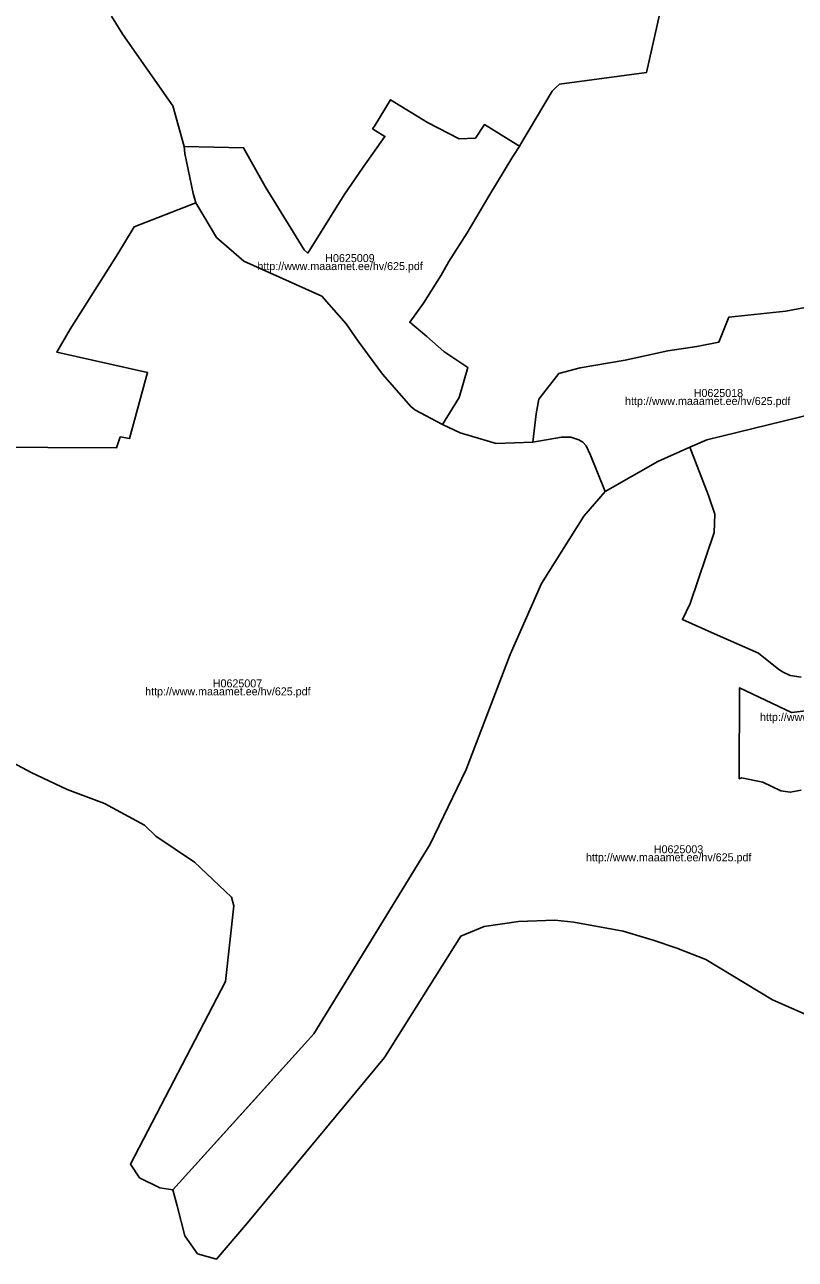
# Model space of a CAD drawing. Extents: x 369010 to 739155, y 6377141 to 6634081.
# Drawn here: x 526588 to 528995, y 6469557 to 6473413 of the extents above; entities that cross this region are included whole.
import ezdxf

# ---------------------------------------------------------------- set-up
doc = ezdxf.new("R2010")
doc.units = 0
for name, color, linetype in [('H_LINK', 7, 'Continuous'), ('H_PIIR', 7, 'Continuous'), ('H_TUNNUS', 7, 'Continuous')]:
    doc.layers.add(name, color=color, linetype=linetype)

msp = doc.modelspace()

# ---------------------------------------------------------------- linework, layer by layer
at = {"layer": 'H_PIIR'}
for points in [[(528589.67, 6473527.89), (528530.48, 6473264.36), (528259.09, 6473227.1101), (528245.84, 6473216.34), (528236.26, 6473205.33), (528138.15, 6473040.7199), (528134.2699, 6473034.71), (528128.4299, 6473036.44), (528023.96, 6473101.2399), (527996.25, 6473058.5499), (527944.85, 6473057.05), (527846.62, 6473108.2099), (527730.9099, 6473178.7101), (527680.44, 6473095.87), (527674.85, 6473088.32), (527683.43, 6473082.8099), (527713.5699, 6473064.27), (527645.0401, 6472967.87), (527586.53, 6472882.22), (527472.5101, 6472699.94), (527461.3, 6472710.46), (527339.8101, 6472907.9299), (527271.7301, 6473029.0799), (527086.72, 6473032.84), (527050.6, 6473159.6301), (526894.58, 6473382.58), (526859.94, 6473440.0801)], [(529107.85, 6472545.1301), (528965.28, 6472517.9799), (528787.09, 6472499.5701), (528756.01, 6472421.36), (528687.22, 6472408.04), (528596.64, 6472394.12), (528463.2701, 6472365.7501), (528323.67, 6472341.3799), (528256.85, 6472323.27), (528194.47, 6472243.2), (528185.5599, 6472197.94), (528175.2199, 6472109.09), (528061.15, 6472104.65), (527948.18, 6472137.89), (527893.4, 6472164.67), (527945.0901, 6472248.6201), (527972, 6472342.43), (527896.95, 6472392.1099), (527843.9699, 6472438.8899), (527791.0801, 6472483.8699), (527833.91, 6472543.07), (527889.0901, 6472630.4299), (527912.86, 6472673.8401), (527970.18, 6472763.52), (528038.15, 6472877.22), (528112.64, 6473001.22), (528134.2699, 6473034.71), (528138.15, 6473040.7199), (528236.26, 6473205.33), (528245.84, 6473216.34), (528259.09, 6473227.1101), (528530.48, 6473264.36), (528589.67, 6473527.89)], [(526859.94, 6473440.0801), (526894.58, 6473382.58), (527050.6, 6473159.6301), (527086.72, 6473032.84), (527088.48, 6473010.92), (527114.61, 6472885.94), (527122.61, 6472856.94), (526930.46, 6472782.2701), (526897.42, 6472726.61), (526874.49, 6472689.58), (526730.06, 6472462.0501), (526688.4401, 6472390.68), (526972.2499, 6472326.9799), (526916.03, 6472120.19), (526886.7599, 6472125.84), (526874.8201, 6472091.0601), (526445.13, 6472093.3199)], [(526445.13, 6472093.3199), (526874.8201, 6472091.0601), (526886.7599, 6472125.84), (526916.03, 6472120.19), (526972.2499, 6472326.9799), (526688.4401, 6472390.68), (526730.06, 6472462.0501), (526874.49, 6472689.58), (526897.42, 6472726.61), (526930.46, 6472782.2701), (527122.61, 6472856.94), (527147.33, 6472815.47), (527187.1, 6472748.7399), (527272.3801, 6472674.51), (527384.2401, 6472624.6599), (527516.04, 6472564.8301), (527592.4599, 6472478.42), (527630.32, 6472424.83), (527705.6301, 6472321.7999), (527794.16, 6472220.2299), (527806.39, 6472210.5501), (527893.4, 6472164.67), (527948.18, 6472137.89), (528061.15, 6472104.65), (528175.2199, 6472109.09), (528265.2399, 6472124.3999), (528294.55, 6472124.7), (528319.5201, 6472116.55), (528332, 6472109.11), (528342.19, 6472097.3901), (528355.7499, 6472068.5301), (528400.9401, 6471955.5101), (528334.4899, 6471877.73), (528202.7, 6471667.88), (528104.13, 6471446.31), (527966.79, 6471086.25), (527855.2205, 6470853.5011), (527491.8389, 6470260.7752), (527050.513, 6469773.4117), (527010.8255, 6469779.7617), (526947.3253, 6469811.5118), (526918.7503, 6469854.3744), (527215.6134, 6470424.288), (527241.0134, 6470660.826), (527234.5083, 6470688.3758), (527118.7757, 6470797.3512), (526998.3927, 6470878.6112), (526962.4093, 6470912.4779), (526837.5257, 6470980.2114), (526721.1088, 6471024.6615), (526608.9253, 6471077.5782), (526481.925, 6471145.3117)], [(529101.44, 6472210.1), (528718.62, 6472116.9799), (528665.93, 6472093.2999), (528565.9601, 6472048.3501), (528400.9401, 6471955.5101), (528355.7499, 6472068.5301), (528342.19, 6472097.3901), (528332, 6472109.11), (528319.5201, 6472116.55), (528294.55, 6472124.7), (528265.2399, 6472124.3999), (528175.2199, 6472109.09), (528185.5599, 6472197.94), (528194.47, 6472243.2), (528256.85, 6472323.27), (528323.67, 6472341.3799), (528463.2701, 6472365.7501), (528596.64, 6472394.12), (528687.22, 6472408.04), (528756.01, 6472421.36), (528787.09, 6472499.5701), (528965.28, 6472517.9799), (529107.85, 6472545.1301)], [(529013.18, 6471374.9899), (528979.0901, 6471380.45), (528956.74, 6471390.73), (528943.3401, 6471398.82), (528879.8201, 6471450.15), (528742.82, 6471510.14), (528642.6501, 6471554.9899), (528667.18, 6471605.6799), (528741.49, 6471827.2899), (528743.76, 6471884.14), (528724.0501, 6471942.44), (528665.93, 6472093.2999), (528718.62, 6472116.9799), (529101.44, 6472210.1)], [(529239.161, 6470228.233), (528923.777, 6470366.8749), (528715.8935, 6470493.3196), (528625.4059, 6470528.2447), (528550.7932, 6470553.6447), (528457.1305, 6470582.2198), (528302.922, 6470609.8737), (528244.4051, 6470615.5573), (528130.1049, 6470612.3823), (528023.7422, 6470596.5073), (527950.717, 6470566.3447), (527712.5915, 6470186.9315), (527283.9657, 6469670.993), (527187.128, 6469556.6927), (527128.3904, 6469574.1553), (527088.7028, 6469629.7179), (527064.8902, 6469723.3806), (527050.513, 6469773.4117), (527299.428, 6470048.2926), (527491.8389, 6470260.7752), (527581.0692, 6470406.3222), (527855.2205, 6470853.5011), (527966.79, 6471086.25), (528104.13, 6471446.31), (528202.7, 6471667.88), (528334.4899, 6471877.73), (528400.9401, 6471955.5101), (528565.9601, 6472048.3501), (528665.93, 6472093.2999), (528724.0501, 6471942.44), (528743.76, 6471884.14), (528741.49, 6471827.2899), (528667.18, 6471605.6799), (528642.6501, 6471554.9899), (528742.82, 6471510.14), (528879.8201, 6471450.15), (528943.3401, 6471398.82), (528956.74, 6471390.73), (528979.0901, 6471380.45), (529013.18, 6471374.9899)], [(529027.5701, 6471269.4401), (528983.26, 6471264.5), (528820.3401, 6471341.35), (528820.14, 6471057.9), (528826.98, 6471060.36), (528893.5699, 6471046.6399), (528950.29, 6471020.2601), (528979.13, 6471015.5401), (529013.1301, 6471021.9901)], [(529013.1301, 6471021.9901), (528979.13, 6471015.5401), (528950.29, 6471020.2601), (528893.5699, 6471046.6399), (528826.98, 6471060.36), (528820.14, 6471057.9), (528820.3401, 6471341.35), (528983.26, 6471264.5), (529027.5701, 6471269.4401)]]:
    msp.add_lwpolyline(points, dxfattribs=at)
msp.add_lwpolyline([(527086.72, 6473032.84), (527271.7301, 6473029.0799), (527339.8101, 6472907.9299), (527461.3, 6472710.46), (527472.5101, 6472699.94), (527586.53, 6472882.22), (527645.0401, 6472967.87), (527713.5699, 6473064.27), (527683.43, 6473082.8099), (527674.85, 6473088.32), (527680.44, 6473095.87), (527730.9099, 6473178.7101), (527846.62, 6473108.2099), (527944.85, 6473057.05), (527996.25, 6473058.5499), (528023.96, 6473101.2399), (528128.4299, 6473036.44), (528134.2699, 6473034.71), (528112.64, 6473001.22), (528038.15, 6472877.22), (527970.18, 6472763.52), (527912.86, 6472673.8401), (527889.0901, 6472630.4299), (527833.91, 6472543.07), (527791.0801, 6472483.8699), (527843.9699, 6472438.8899), (527896.95, 6472392.1099), (527972, 6472342.43), (527945.0901, 6472248.6201), (527893.4, 6472164.67), (527806.39, 6472210.5501), (527794.16, 6472220.2299), (527705.6301, 6472321.7999), (527630.32, 6472424.83), (527592.4599, 6472478.42), (527516.04, 6472564.8301), (527384.2401, 6472624.6599), (527272.3801, 6472674.51), (527187.1, 6472748.7399), (527147.33, 6472815.47), (527122.61, 6472856.94), (527114.61, 6472885.94), (527088.48, 6473010.92)], close=True, dxfattribs=at)

# ---------------------------------------------------------------- texts
at = {"layer": 'H_LINK'}
for rotation, p in [(360, (527315.2209, 6472646.69)), (0, (528463.4483, 6472225.3201)), (0, (528885.0457, 6471238.1925)), (0, (528341.4237, 6470799.9963))]:
    msp.add_text('http://www.maaamet.ee/hv/625.pdf', height=25, rotation=rotation, dxfattribs=at).set_placement(p)
msp.add_text('http://www.maaamet.ee/hv/625.pdf', height=25, dxfattribs=at).set_placement((526964.6078, 6471318.2157))
at = {"layer": 'H_TUNNUS'}
for s, rotation, p in [('H0625009', 360, (527527.0755, 6472671.69)), ('H0625018', 0, (528677.8022, 6472250.3201)), ('H0625003', 0, (528553.2782, 6470824.9963))]:
    msp.add_text(s, height=25, rotation=rotation, dxfattribs=at).set_placement(p)
msp.add_text('H0625007', height=25, dxfattribs=at).set_placement((527175.8367, 6471343.2157))

doc.saveas('drawing.dxf')
